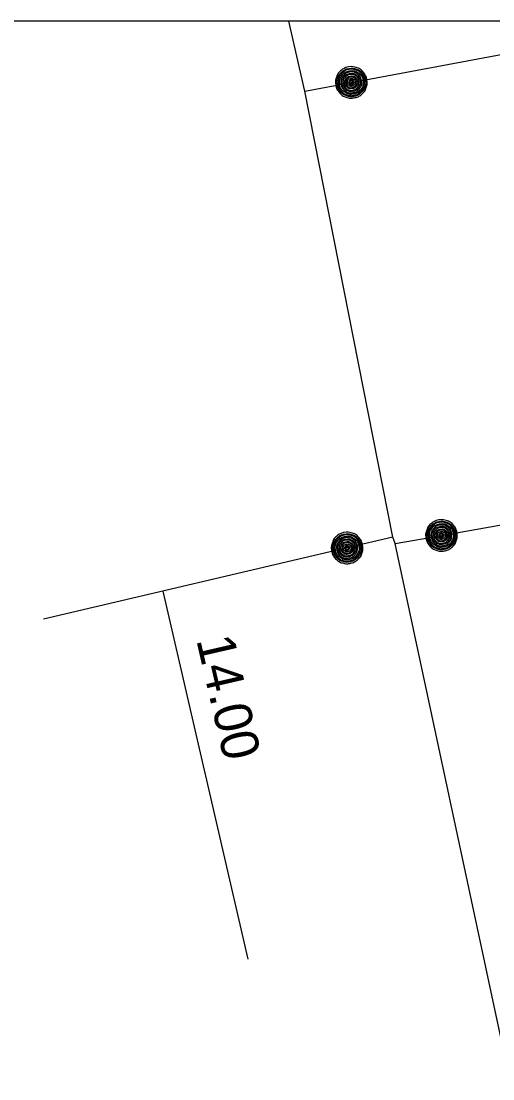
# Model space of a CAD drawing. Extents: x -820257 to -819974, y -1070894 to -1070484.
# Drawn here: x -820221.8 to -820206.79, y -1070518.08 to -1070484.4 of the extents above; entities that cross this region are included whole.
import ezdxf

# ---------------------------------------------------------------- set-up
doc = ezdxf.new("R2010")
doc.units = 0
for name, color, linetype in [('Default', 7, 'Continuous'), ('Oměrka vodovodu', 7, 'Continuous'), ('Oměrka-text', 7, 'Continuous'), ('Přípojka vodovodu', 7, 'Continuous'), ('Přípojkový uzávěr', 7, 'Continuous'), ('Roz-řad', 7, 'Continuous')]:
    doc.layers.add(name, color=color, linetype=linetype)

msp = doc.modelspace()

# ---------------------------------------------------------------- linework, layer by layer
at = {"layer": 'Default'}
msp.add_lwpolyline([(-819975.603, -1070484.403), (-820256.81, -1070484.403), (-820256.81, -1070893.932)], dxfattribs=at)
at = {"layer": 'Oměrka vodovodu'}
msp.add_line((-820217.288, -1070502.553), (-820214.588, -1070514.268), dxfattribs=at)
at = {"layer": 'Přípojka vodovodu'}
for points in [[(-820212.767, -1070486.628), (-820211.291, -1070486.353), (-820200.838, -1070484.403)], [(-820209.898, -1070501.039), (-820208.421, -1070500.777), (-820193.65, -1070498.152)], [(-820209.965, -1070500.833), (-820211.426, -1070501.176), (-820221.091, -1070503.446)]]:
    msp.add_lwpolyline(points, dxfattribs=at)
at = {"layer": 'Přípojkový uzávěr'}
for points in [[(-820211.383, -1070485.861), (-820211.259, -1070485.838), (-820211.13, -1070485.88), (-820211.001, -1070485.921), (-820210.912, -1070486.027), (-820210.824, -1070486.133), (-820210.8, -1070486.262), (-820210.776, -1070486.389), (-820210.819, -1070486.518), (-820210.862, -1070486.647), (-820210.967, -1070486.734), (-820211.072, -1070486.821), (-820211.2, -1070486.844), (-820211.327, -1070486.868), (-820211.456, -1070486.825), (-820211.586, -1070486.782), (-820211.672, -1070486.677), (-820211.759, -1070486.573), (-820211.783, -1070486.445), (-820211.807, -1070486.316), (-820211.763, -1070486.186), (-820211.719, -1070486.055), (-820211.613, -1070485.97), (-820211.508, -1070485.885), (-820211.383, -1070485.861)], [(-820211.375, -1070485.907), (-820211.487, -1070485.928), (-820211.583, -1070486.006), (-820211.679, -1070486.083), (-820211.719, -1070486.201), (-820211.758, -1070486.32), (-820211.737, -1070486.436), (-820211.715, -1070486.552), (-820211.637, -1070486.647), (-820211.558, -1070486.742), (-820211.441, -1070486.781), (-820211.324, -1070486.82), (-820211.209, -1070486.798), (-820211.092, -1070486.777), (-820210.997, -1070486.698), (-820210.902, -1070486.619), (-820210.863, -1070486.503), (-820210.824, -1070486.386), (-820210.846, -1070486.27), (-820210.867, -1070486.154), (-820210.948, -1070486.058), (-820211.028, -1070485.962), (-820211.145, -1070485.924), (-820211.262, -1070485.887), (-820211.375, -1070485.907)], [(-820211.368, -1070485.941), (-820211.264, -1070485.922), (-820211.156, -1070485.956), (-820211.048, -1070485.991), (-820210.974, -1070486.08), (-820210.899, -1070486.168), (-820210.879, -1070486.276), (-820210.859, -1070486.384), (-820210.895, -1070486.492), (-820210.931, -1070486.6), (-820211.019, -1070486.672), (-820211.107, -1070486.745), (-820211.215, -1070486.765), (-820211.321, -1070486.785), (-820211.43, -1070486.749), (-820211.538, -1070486.713), (-820211.611, -1070486.625), (-820211.683, -1070486.537), (-820211.703, -1070486.43), (-820211.723, -1070486.322), (-820211.686, -1070486.213), (-820211.65, -1070486.103), (-820211.561, -1070486.032), (-820211.472, -1070485.96), (-820211.368, -1070485.941)], [(-820211.361, -1070485.984), (-820211.514, -1070486.013), (-820211.601, -1070486.141), (-820211.688, -1070486.269), (-820211.66, -1070486.422), (-820211.631, -1070486.575), (-820211.503, -1070486.662), (-820211.375, -1070486.75), (-820211.223, -1070486.722), (-820211.07, -1070486.693), (-820210.982, -1070486.565), (-820210.894, -1070486.437), (-820210.922, -1070486.285), (-820210.951, -1070486.131), (-820211.078, -1070486.043), (-820211.206, -1070485.955), (-820211.361, -1070485.984)], [(-820211.352, -1070486.029), (-820211.218, -1070486.004), (-820211.106, -1070486.081), (-820210.995, -1070486.158), (-820210.97, -1070486.292), (-820210.945, -1070486.426), (-820211.021, -1070486.538), (-820211.098, -1070486.65), (-820211.232, -1070486.675), (-820211.367, -1070486.7), (-820211.478, -1070486.623), (-820211.59, -1070486.546), (-820211.615, -1070486.412), (-820211.64, -1070486.278), (-820211.563, -1070486.166), (-820211.487, -1070486.055), (-820211.352, -1070486.029)], [(-820211.345, -1070486.068), (-820211.463, -1070486.09), (-820211.531, -1070486.189), (-820211.598, -1070486.287), (-820211.576, -1070486.405), (-820211.554, -1070486.523), (-820211.456, -1070486.59), (-820211.357, -1070486.658), (-820211.239, -1070486.636), (-820211.122, -1070486.614), (-820211.054, -1070486.515), (-820210.987, -1070486.417), (-820211.009, -1070486.299), (-820211.031, -1070486.182), (-820211.129, -1070486.114), (-820211.227, -1070486.046), (-820211.345, -1070486.068)], [(-820211.337, -1070486.107), (-820211.234, -1070486.088), (-820211.149, -1070486.147), (-820211.064, -1070486.205), (-820211.045, -1070486.307), (-820211.026, -1070486.409), (-820211.085, -1070486.494), (-820211.144, -1070486.58), (-820211.246, -1070486.599), (-820211.347, -1070486.618), (-820211.432, -1070486.559), (-820211.518, -1070486.501), (-820211.537, -1070486.399), (-820211.556, -1070486.297), (-820211.498, -1070486.212), (-820211.44, -1070486.126), (-820211.337, -1070486.107)], [(-820211.329, -1070486.153), (-820211.412, -1070486.168), (-820211.459, -1070486.237), (-820211.507, -1070486.307), (-820211.491, -1070486.39), (-820211.476, -1070486.473), (-820211.407, -1070486.52), (-820211.338, -1070486.568), (-820211.254, -1070486.552), (-820211.172, -1070486.537), (-820211.124, -1070486.467), (-820211.077, -1070486.398), (-820211.092, -1070486.315), (-820211.108, -1070486.232), (-820211.177, -1070486.185), (-820211.246, -1070486.137), (-820211.329, -1070486.153)], [(-820211.323, -1070486.187), (-820211.253, -1070486.174), (-820211.196, -1070486.213), (-820211.139, -1070486.252), (-820211.126, -1070486.322), (-820211.113, -1070486.391), (-820211.153, -1070486.448), (-820211.192, -1070486.505), (-820211.261, -1070486.518), (-820211.33, -1070486.531), (-820211.387, -1070486.492), (-820211.444, -1070486.452), (-820211.457, -1070486.383), (-820211.47, -1070486.314), (-820211.431, -1070486.257), (-820211.392, -1070486.2), (-820211.323, -1070486.187)], [(-820211.315, -1070486.23), (-820211.365, -1070486.24), (-820211.394, -1070486.282), (-820211.424, -1070486.325), (-820211.414, -1070486.376), (-820211.405, -1070486.427), (-820211.362, -1070486.456), (-820211.319, -1070486.485), (-820211.269, -1070486.476), (-820211.217, -1070486.466), (-820211.188, -1070486.423), (-820211.159, -1070486.381), (-820211.168, -1070486.33), (-820211.178, -1070486.279), (-820211.22, -1070486.25), (-820211.263, -1070486.22), (-820211.315, -1070486.23)], [(-820211.306, -1070486.276), (-820211.273, -1070486.27), (-820211.247, -1070486.288), (-820211.221, -1070486.306), (-820211.215, -1070486.339), (-820211.209, -1070486.37), (-820211.227, -1070486.397), (-820211.245, -1070486.424), (-820211.277, -1070486.43), (-820211.309, -1070486.436), (-820211.336, -1070486.417), (-820211.363, -1070486.399), (-820211.368, -1070486.367), (-820211.375, -1070486.335), (-820211.356, -1070486.308), (-820211.338, -1070486.282), (-820211.306, -1070486.276)], [(-820211.3, -1070486.307), (-820211.319, -1070486.31), (-820211.33, -1070486.326), (-820211.341, -1070486.342), (-820211.338, -1070486.361), (-820211.334, -1070486.381), (-820211.318, -1070486.392), (-820211.302, -1070486.403), (-820211.283, -1070486.399), (-820211.263, -1070486.395), (-820211.253, -1070486.379), (-820211.242, -1070486.364), (-820211.246, -1070486.344), (-820211.249, -1070486.325), (-820211.265, -1070486.314), (-820211.281, -1070486.303), (-820211.3, -1070486.307)], [(-820208.509, -1070500.285), (-820208.385, -1070500.263), (-820208.256, -1070500.306), (-820208.127, -1070500.348), (-820208.039, -1070500.455), (-820207.952, -1070500.561), (-820207.929, -1070500.69), (-820207.906, -1070500.818), (-820207.95, -1070500.947), (-820207.994, -1070501.075), (-820208.1, -1070501.161), (-820208.206, -1070501.247), (-820208.334, -1070501.27), (-820208.462, -1070501.292), (-820208.59, -1070501.248), (-820208.719, -1070501.204), (-820208.805, -1070501.099), (-820208.891, -1070500.993), (-820208.913, -1070500.865), (-820208.936, -1070500.736), (-820208.891, -1070500.606), (-820208.846, -1070500.476), (-820208.74, -1070500.392), (-820208.634, -1070500.307), (-820208.509, -1070500.285)], [(-820208.501, -1070500.331), (-820208.613, -1070500.351), (-820208.71, -1070500.428), (-820208.806, -1070500.504), (-820208.847, -1070500.622), (-820208.888, -1070500.74), (-820208.867, -1070500.857), (-820208.847, -1070500.973), (-820208.769, -1070501.068), (-820208.692, -1070501.164), (-820208.575, -1070501.204), (-820208.458, -1070501.244), (-820208.342, -1070501.223), (-820208.226, -1070501.203), (-820208.13, -1070501.125), (-820208.034, -1070501.047), (-820207.994, -1070500.931), (-820207.954, -1070500.814), (-820207.975, -1070500.698), (-820207.996, -1070500.582), (-820208.075, -1070500.485), (-820208.155, -1070500.388), (-820208.272, -1070500.35), (-820208.388, -1070500.311), (-820208.501, -1070500.331)], [(-820208.495, -1070500.365), (-820208.391, -1070500.346), (-820208.283, -1070500.382), (-820208.175, -1070500.418), (-820208.101, -1070500.507), (-820208.028, -1070500.596), (-820208.009, -1070500.704), (-820207.99, -1070500.812), (-820208.026, -1070500.919), (-820208.063, -1070501.027), (-820208.152, -1070501.099), (-820208.241, -1070501.171), (-820208.348, -1070501.19), (-820208.455, -1070501.209), (-820208.563, -1070501.172), (-820208.672, -1070501.135), (-820208.743, -1070501.047), (-820208.815, -1070500.958), (-820208.834, -1070500.851), (-820208.853, -1070500.743), (-820208.815, -1070500.634), (-820208.778, -1070500.525), (-820208.688, -1070500.454), (-820208.599, -1070500.383), (-820208.495, -1070500.365)], [(-820208.488, -1070500.408), (-820208.642, -1070500.436), (-820208.73, -1070500.563), (-820208.818, -1070500.69), (-820208.79, -1070500.843), (-820208.763, -1070500.996), (-820208.636, -1070501.085), (-820208.508, -1070501.174), (-820208.357, -1070501.147), (-820208.203, -1070501.119), (-820208.114, -1070500.992), (-820208.025, -1070500.865), (-820208.052, -1070500.712), (-820208.079, -1070500.559), (-820208.206, -1070500.47), (-820208.332, -1070500.381), (-820208.488, -1070500.408)], [(-820208.48, -1070500.453), (-820208.345, -1070500.429), (-820208.234, -1070500.507), (-820208.123, -1070500.585), (-820208.099, -1070500.719), (-820208.075, -1070500.853), (-820208.153, -1070500.964), (-820208.231, -1070501.076), (-820208.365, -1070501.1), (-820208.5, -1070501.123), (-820208.611, -1070501.046), (-820208.722, -1070500.968), (-820208.745, -1070500.834), (-820208.769, -1070500.7), (-820208.692, -1070500.589), (-820208.614, -1070500.477), (-820208.48, -1070500.453)], [(-820208.473, -1070500.492), (-820208.591, -1070500.513), (-820208.659, -1070500.611), (-820208.727, -1070500.709), (-820208.706, -1070500.827), (-820208.686, -1070500.945), (-820208.588, -1070501.013), (-820208.49, -1070501.082), (-820208.372, -1070501.061), (-820208.254, -1070501.04), (-820208.186, -1070500.942), (-820208.117, -1070500.844), (-820208.138, -1070500.726), (-820208.159, -1070500.608), (-820208.257, -1070500.54), (-820208.354, -1070500.471), (-820208.473, -1070500.492)], [(-820211.54, -1070500.689), (-820211.418, -1070500.66), (-820211.287, -1070500.696), (-820211.155, -1070500.731), (-820211.062, -1070500.833), (-820210.969, -1070500.935), (-820210.939, -1070501.062), (-820210.909, -1070501.189), (-820210.946, -1070501.319), (-820210.983, -1070501.45), (-820211.084, -1070501.542), (-820211.185, -1070501.633), (-820211.312, -1070501.663), (-820211.438, -1070501.692), (-820211.569, -1070501.655), (-820211.7, -1070501.619), (-820211.791, -1070501.518), (-820211.883, -1070501.417), (-820211.912, -1070501.291), (-820211.942, -1070501.163), (-820211.904, -1070501.031), (-820211.866, -1070500.898), (-820211.765, -1070500.808), (-820211.663, -1070500.718), (-820211.54, -1070500.689)], [(-820211.53, -1070500.735), (-820211.641, -1070500.761), (-820211.733, -1070500.843), (-820211.825, -1070500.924), (-820211.859, -1070501.044), (-820211.894, -1070501.164), (-820211.867, -1070501.28), (-820211.84, -1070501.395), (-820211.757, -1070501.486), (-820211.674, -1070501.577), (-820211.555, -1070501.61), (-820211.437, -1070501.644), (-820211.322, -1070501.617), (-820211.207, -1070501.59), (-820211.116, -1070501.507), (-820211.024, -1070501.424), (-820210.991, -1070501.306), (-820210.957, -1070501.187), (-820210.984, -1070501.073), (-820211.011, -1070500.957), (-820211.096, -1070500.865), (-820211.181, -1070500.773), (-820211.3, -1070500.741), (-820211.418, -1070500.709), (-820211.53, -1070500.735)], [(-820211.522, -1070500.768), (-820211.419, -1070500.744), (-820211.309, -1070500.774), (-820211.2, -1070500.803), (-820211.121, -1070500.889), (-820211.043, -1070500.974), (-820211.018, -1070501.081), (-820210.993, -1070501.187), (-820211.023, -1070501.296), (-820211.054, -1070501.406), (-820211.139, -1070501.482), (-820211.224, -1070501.559), (-820211.33, -1070501.584), (-820211.436, -1070501.609), (-820211.546, -1070501.578), (-820211.656, -1070501.547), (-820211.732, -1070501.463), (-820211.808, -1070501.378), (-820211.833, -1070501.272), (-820211.858, -1070501.165), (-820211.827, -1070501.054), (-820211.795, -1070500.943), (-820211.71, -1070500.868), (-820211.624, -1070500.792), (-820211.522, -1070500.768)], [(-820211.512, -1070500.811), (-820211.664, -1070500.847), (-820211.745, -1070500.979), (-820211.826, -1070501.111), (-820211.791, -1070501.262), (-820211.755, -1070501.413), (-820211.623, -1070501.495), (-820211.491, -1070501.576), (-820211.341, -1070501.541), (-820211.189, -1070501.505), (-820211.107, -1070501.374), (-820211.025, -1070501.242), (-820211.06, -1070501.091), (-820211.096, -1070500.939), (-820211.227, -1070500.857), (-820211.359, -1070500.775), (-820211.512, -1070500.811)], [(-820208.465, -1070500.531), (-820208.362, -1070500.513), (-820208.278, -1070500.572), (-820208.193, -1070500.632), (-820208.175, -1070500.734), (-820208.157, -1070500.836), (-820208.216, -1070500.921), (-820208.276, -1070501.005), (-820208.378, -1070501.023), (-820208.479, -1070501.041), (-820208.564, -1070500.982), (-820208.649, -1070500.923), (-820208.667, -1070500.821), (-820208.685, -1070500.719), (-820208.627, -1070500.634), (-820208.568, -1070500.549), (-820208.465, -1070500.531)], [(-820208.457, -1070500.577), (-820208.54, -1070500.592), (-820208.588, -1070500.66), (-820208.637, -1070500.729), (-820208.622, -1070500.812), (-820208.607, -1070500.896), (-820208.538, -1070500.944), (-820208.469, -1070500.992), (-820208.386, -1070500.977), (-820208.304, -1070500.962), (-820208.255, -1070500.893), (-820208.207, -1070500.824), (-820208.222, -1070500.741), (-820208.237, -1070500.658), (-820208.305, -1070500.61), (-820208.374, -1070500.562), (-820208.457, -1070500.577)], [(-820208.451, -1070500.611), (-820208.382, -1070500.599), (-820208.325, -1070500.638), (-820208.268, -1070500.678), (-820208.256, -1070500.747), (-820208.244, -1070500.817), (-820208.284, -1070500.874), (-820208.324, -1070500.93), (-820208.392, -1070500.943), (-820208.462, -1070500.955), (-820208.518, -1070500.915), (-820208.575, -1070500.876), (-820208.588, -1070500.806), (-820208.6, -1070500.737), (-820208.56, -1070500.68), (-820208.52, -1070500.623), (-820208.451, -1070500.611)], [(-820208.444, -1070500.654), (-820208.494, -1070500.663), (-820208.524, -1070500.706), (-820208.553, -1070500.748), (-820208.544, -1070500.799), (-820208.535, -1070500.85), (-820208.493, -1070500.88), (-820208.45, -1070500.909), (-820208.4, -1070500.9), (-820208.348, -1070500.891), (-820208.319, -1070500.849), (-820208.289, -1070500.806), (-820208.298, -1070500.755), (-820208.307, -1070500.704), (-820208.349, -1070500.675), (-820208.392, -1070500.645), (-820208.444, -1070500.654)], [(-820208.435, -1070500.7), (-820208.403, -1070500.695), (-820208.377, -1070500.713), (-820208.351, -1070500.731), (-820208.345, -1070500.764), (-820208.339, -1070500.795), (-820208.357, -1070500.822), (-820208.375, -1070500.848), (-820208.408, -1070500.854), (-820208.44, -1070500.86), (-820208.466, -1070500.841), (-820208.493, -1070500.823), (-820208.499, -1070500.791), (-820208.504, -1070500.758), (-820208.486, -1070500.732), (-820208.467, -1070500.706), (-820208.435, -1070500.7)], [(-820208.43, -1070500.731), (-820208.449, -1070500.735), (-820208.46, -1070500.75), (-820208.471, -1070500.766), (-820208.468, -1070500.786), (-820208.464, -1070500.805), (-820208.449, -1070500.816), (-820208.433, -1070500.827), (-820208.413, -1070500.823), (-820208.394, -1070500.82), (-820208.383, -1070500.804), (-820208.372, -1070500.788), (-820208.376, -1070500.769), (-820208.379, -1070500.749), (-820208.395, -1070500.739), (-820208.41, -1070500.728), (-820208.43, -1070500.731)], [(-820211.502, -1070500.856), (-820211.368, -1070500.824), (-820211.253, -1070500.896), (-820211.138, -1070500.968), (-820211.107, -1070501.1), (-820211.076, -1070501.233), (-820211.148, -1070501.348), (-820211.219, -1070501.463), (-820211.352, -1070501.495), (-820211.485, -1070501.526), (-820211.6, -1070501.454), (-820211.715, -1070501.383), (-820211.746, -1070501.25), (-820211.777, -1070501.118), (-820211.706, -1070501.002), (-820211.635, -1070500.887), (-820211.502, -1070500.856)], [(-820211.493, -1070500.894), (-820211.61, -1070500.922), (-820211.672, -1070501.023), (-820211.735, -1070501.125), (-820211.708, -1070501.241), (-820211.68, -1070501.358), (-820211.579, -1070501.421), (-820211.478, -1070501.484), (-820211.361, -1070501.456), (-820211.244, -1070501.429), (-820211.181, -1070501.327), (-820211.118, -1070501.226), (-820211.146, -1070501.109), (-820211.173, -1070500.993), (-820211.274, -1070500.93), (-820211.375, -1070500.867), (-820211.493, -1070500.894)], [(-820211.483, -1070500.933), (-820211.381, -1070500.909), (-820211.293, -1070500.963), (-820211.206, -1070501.018), (-820211.182, -1070501.119), (-820211.158, -1070501.22), (-820211.213, -1070501.308), (-820211.268, -1070501.396), (-820211.369, -1070501.419), (-820211.469, -1070501.443), (-820211.557, -1070501.389), (-820211.645, -1070501.334), (-820211.669, -1070501.234), (-820211.693, -1070501.132), (-820211.639, -1070501.044), (-820211.585, -1070500.957), (-820211.483, -1070500.933)], [(-820211.473, -1070500.978), (-820211.555, -1070500.997), (-820211.599, -1070501.068), (-820211.643, -1070501.14), (-820211.624, -1070501.222), (-820211.605, -1070501.304), (-820211.533, -1070501.348), (-820211.462, -1070501.393), (-820211.38, -1070501.373), (-820211.298, -1070501.354), (-820211.254, -1070501.283), (-820211.209, -1070501.211), (-820211.228, -1070501.129), (-820211.248, -1070501.047), (-820211.319, -1070501.003), (-820211.39, -1070500.959), (-820211.473, -1070500.978)], [(-820211.465, -1070501.012), (-820211.396, -1070500.995), (-820211.337, -1070501.032), (-820211.278, -1070501.069), (-820211.262, -1070501.137), (-820211.246, -1070501.206), (-820211.283, -1070501.265), (-820211.32, -1070501.324), (-820211.388, -1070501.34), (-820211.456, -1070501.356), (-820211.515, -1070501.319), (-820211.574, -1070501.283), (-820211.59, -1070501.214), (-820211.606, -1070501.146), (-820211.57, -1070501.087), (-820211.533, -1070501.028), (-820211.465, -1070501.012)], [(-820211.455, -1070501.054), (-820211.505, -1070501.066), (-820211.532, -1070501.11), (-820211.559, -1070501.154), (-820211.547, -1070501.205), (-820211.535, -1070501.255), (-820211.491, -1070501.282), (-820211.447, -1070501.309), (-820211.397, -1070501.298), (-820211.347, -1070501.286), (-820211.319, -1070501.242), (-820211.292, -1070501.198), (-820211.304, -1070501.147), (-820211.316, -1070501.097), (-820211.359, -1070501.07), (-820211.403, -1070501.042), (-820211.455, -1070501.054)], [(-820211.444, -1070501.1), (-820211.412, -1070501.092), (-820211.385, -1070501.109), (-820211.358, -1070501.126), (-820211.35, -1070501.158), (-820211.343, -1070501.19), (-820211.359, -1070501.217), (-820211.376, -1070501.245), (-820211.408, -1070501.252), (-820211.44, -1070501.259), (-820211.467, -1070501.242), (-820211.495, -1070501.225), (-820211.502, -1070501.194), (-820211.51, -1070501.162), (-820211.492, -1070501.134), (-820211.475, -1070501.107), (-820211.444, -1070501.1)], [(-820211.437, -1070501.13), (-820211.456, -1070501.135), (-820211.466, -1070501.151), (-820211.476, -1070501.167), (-820211.472, -1070501.187), (-820211.467, -1070501.206), (-820211.451, -1070501.216), (-820211.434, -1070501.226), (-820211.415, -1070501.222), (-820211.396, -1070501.217), (-820211.386, -1070501.201), (-820211.376, -1070501.184), (-820211.38, -1070501.165), (-820211.385, -1070501.146), (-820211.401, -1070501.136), (-820211.417, -1070501.126), (-820211.437, -1070501.13)]]:
    msp.add_open_spline(points, degree=3, dxfattribs=at)
at = {"layer": 'Roz-řad'}
msp.add_lwpolyline([(-820192.294, -1070583.934), (-820204.367, -1070525.825), (-820206.422, -1070517.249), (-820209.898, -1070501.039), (-820209.965, -1070500.833), (-820212.767, -1070486.628), (-820213.283, -1070484.403)], dxfattribs=at)

# ---------------------------------------------------------------- texts
at = {"layer": 'Oměrka-text'}
msp.add_text('14.00', height=1.2, rotation=282.9785, dxfattribs=at).set_placement((-820216.232, -1070504.098))

doc.saveas('drawing.dxf')
